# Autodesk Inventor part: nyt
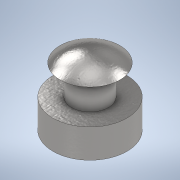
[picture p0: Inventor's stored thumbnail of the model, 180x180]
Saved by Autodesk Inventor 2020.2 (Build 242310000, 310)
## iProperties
Created: 2020-04
Part Number: nyt
Material: Steel, Galvanized
Document SubType Name: Modeling
Designer: freem
Density: 7.85 g/cm^3
Appearance: Galvanized
Author: freem
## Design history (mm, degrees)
sketch "Sketch1"
  geometry: L1 (0, 0)-(0, 5); L2 (0, 5)-(3.9, 5); L3 (3.9, 5)-(3.9, 2.5); L4 (3.9, 2.5)-(7.9, 2.5); L5 (7.9, 2.5)-(7.9, 4.044); L6 (9.4, 0)-(0, 0); L7 (9.4, 0)-(9.4, 11.352); A1 r 6.2 centre (3.2, 0) between (9.4, 0) and (7.9, 4.044)
  constraints: 14 end point, 4 perpendicular, 2 point on circle, 2 vertical, 1 centre point, 1 horizontal, 1 point on line, 1 tangent
  dimensions: "d2" = 7.9 distance between parallel lines of L1 L5; "d5" = 5 diameter of L4 L6; "d6" = 10 diameter of L2 L6; "d7" = 3.9 distance between parallel lines of L1 L3; "d8" = 6.2 radius of A1; "d9" = 9.4 distance from line of L1 L7.start
revolve "Revolution1" sketch "Sketch1" stored, may be unused: angle "d10" = 90 deg
body "Solid1"
